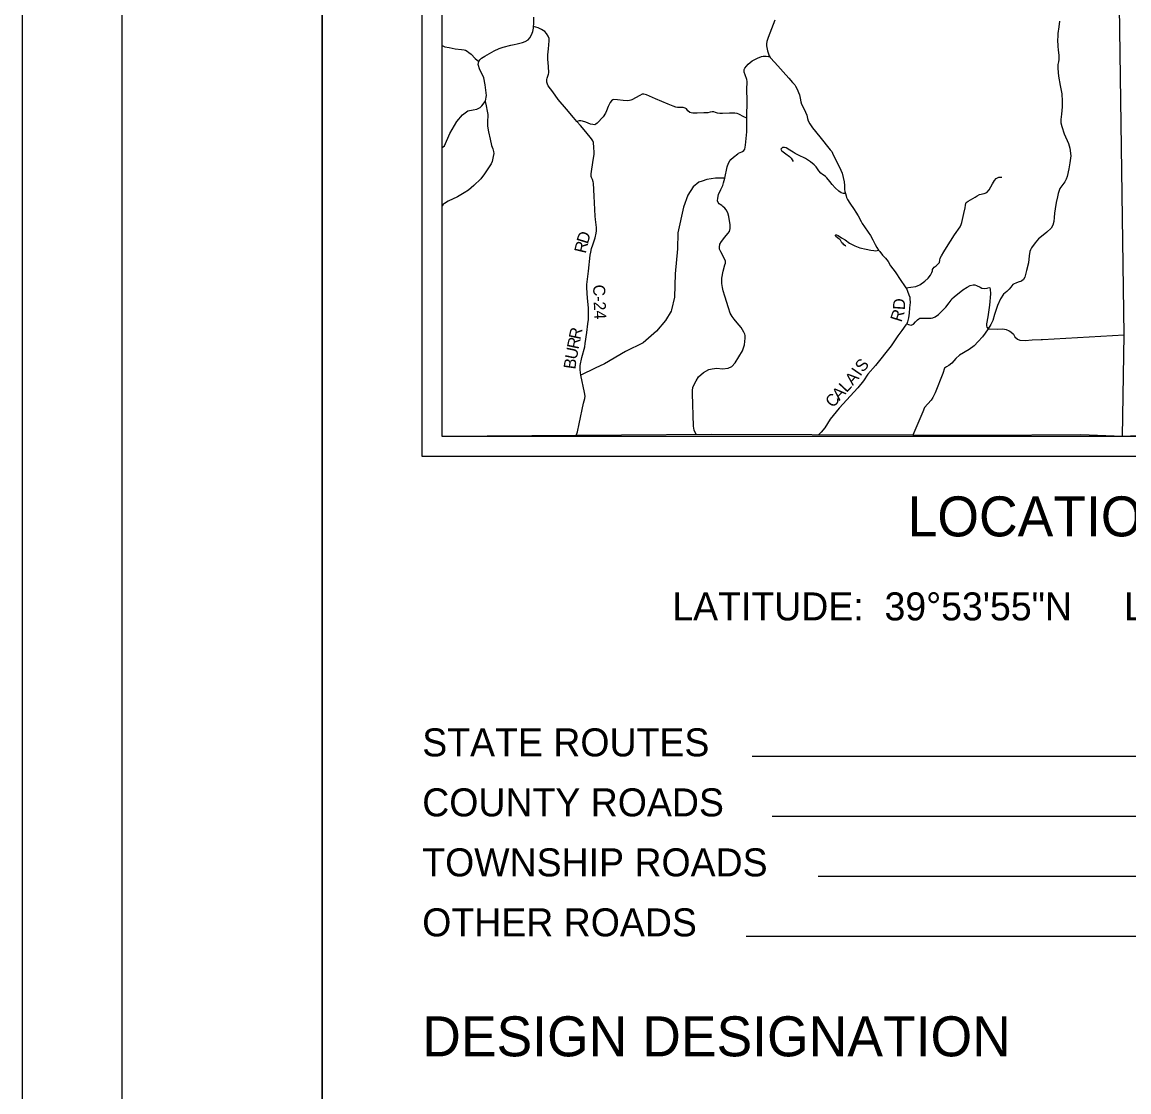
# Model space of a CAD drawing. Extents: x 0 to 2329303, y 0 to 694397.
# Drawn here: x 0 to 5.53, y 10.82 to 16.17 of the extents above; entities that cross this region are included whole.
import ezdxf

# ---------------------------------------------------------------- set-up
doc = ezdxf.new("R2010")
doc.units = 0
for name, color, linetype in [('GM_X_County_Road', 7, 'Continuous'), ('GM_X_County_Road_Text', 7, 'Continuous'), ('GM_X_State_Route', 7, 'Continuous'), ('GM_X_Township', 7, 'Continuous'), ('GM_X_Township_Road', 7, 'Continuous'), ('GM_X_Township_ROW', 7, 'Continuous'), ('SH_Border', 7, 'Continuous'), ('SH_Cut_Line', 7, 'Continuous'), ('SH_Data', 7, 'Continuous')]:
    doc.layers.add(name, color=color, linetype=linetype)

msp = doc.modelspace()

# ---------------------------------------------------------------- linework, layer by layer
at = {"layer": 'GM_X_County_Road'}
for points in [[(3.7623, 16.1817), (3.7466, 16.1383), (3.7289, 16.0945), (3.7227, 16.0744), (3.7203, 16.0635), (3.7204, 16.0523), (3.7266, 16.0275), (3.7315, 16.0135), (3.734, 16.0023)], [(2.77, 14.1049), (2.7767, 14.1234), (2.7842, 14.1622), (2.8067, 14.2655), (2.8125, 14.2901), (2.8138, 14.3009), (2.8114, 14.3189), (2.7927, 14.4063), (2.7892, 14.433), (2.7898, 14.4547), (2.7972, 14.495), (2.8123, 14.5475), (2.8145, 14.5652), (2.8233, 14.6198), (2.8286, 14.6635), (2.8312, 14.6844), (2.8319, 14.6992), (2.8318, 14.7124), (2.8304, 14.7429), (2.8265, 14.791), (2.8221, 14.8435), (2.8228, 14.8595), (2.8311, 14.9265), (2.8397, 15.0055), (2.8424, 15.0212), (2.8463, 15.04), (2.8534, 15.0585), (2.8651, 15.0931), (2.8702, 15.1164), (2.8717, 15.1288), (2.8716, 15.1453), (2.8665, 15.1845), (2.864, 15.2021), (2.8592, 15.3019), (2.8564, 15.3656), (2.8547, 15.3736), (2.8506, 15.3844), (2.8462, 15.394), (2.8445, 15.4004), (2.8448, 15.4128), (2.8551, 15.4811), (2.859, 15.5091), (2.8593, 15.522), (2.8579, 15.5444), (2.8561, 15.5693), (2.8537, 15.5781), (2.8468, 15.5888), (2.8177, 15.6227), (2.7918, 15.6542), (2.7733, 15.6749), (2.7563, 15.6944), (2.7216, 15.7366), (2.6796, 15.7844), (2.6525, 15.8223), (2.6298, 15.8538), (2.6266, 15.8614), (2.6237, 15.8706), (2.6232, 15.8846), (2.6248, 15.8914), (2.6279, 15.9015), (2.631, 15.9111), (2.6322, 15.9187), (2.6307, 15.9492), (2.6277, 15.9856), (2.6283, 16.0081), (2.6313, 16.0374), (2.6342, 16.0779), (2.6341, 16.0899), (2.6301, 16.1015), (2.6216, 16.1143), (2.6127, 16.1242), (2.5962, 16.1353), (2.5797, 16.1432), (2.5569, 16.1499)], [(3.734, 16.0023), (3.74, 15.9947), (3.7626, 15.9696), (3.8321, 15.8912), (3.8507, 15.8705), (3.8619, 15.8585), (3.8668, 15.8518), (3.8729, 15.8394), (3.8855, 15.8078), (3.8893, 15.7918), (3.8934, 15.773), (3.8967, 15.761), (3.904, 15.747), (3.9162, 15.7211), (3.9219, 15.7063), (3.926, 15.6899), (3.9293, 15.6779), (3.9378, 15.6627), (3.9516, 15.6435), (3.988, 15.5977), (4.0397, 15.5332), (4.0469, 15.524), (4.0514, 15.516), (4.064, 15.4877), (4.0867, 15.4457), (4.099, 15.4158), (4.1051, 15.3942), (4.1097, 15.3725), (4.111, 15.3553), (4.1111, 15.3429), (4.1116, 15.3341), (4.1128, 15.3253), (4.1153, 15.3149), (4.119, 15.3029), (4.1215, 15.2953), (4.1255, 15.2853), (4.1381, 15.2657), (4.1591, 15.2342), (4.1681, 15.2207), (4.179, 15.2027), (4.194, 15.1748), (4.1997, 15.1644), (4.211, 15.148), (4.2296, 15.1205), (4.241, 15.1042), (4.2523, 15.0822), (4.2649, 15.059), (4.2726, 15.0447), (4.2815, 15.0319), (4.2872, 15.0247), (4.3017, 15.0068), (4.3159, 14.9905), (4.3288, 14.9741), (4.341, 14.9522), (4.364, 14.9223), (4.3923, 14.8804), (4.4109, 14.8533), (4.4182, 14.8425), (4.4219, 14.8361), (4.4264, 14.8257), (4.4333, 14.8082), (4.437, 14.7958), (4.4382, 14.7882), (4.4388, 14.7697), (4.4366, 14.7428), (4.4335, 14.716), (4.4309, 14.6927), (4.4278, 14.6794), (4.4258, 14.6734), (4.4223, 14.6634), (4.418, 14.6572), (4.3973, 14.6295), (4.3783, 14.6033), (4.3439, 14.5522), (4.2651, 14.4544), (4.2277, 14.4117), (4.2057, 14.3783), (4.1778, 14.3431), (4.0851, 14.2412), (4.0388, 14.1855), (4.0119, 14.1435), (3.9936, 14.121), (3.9859, 14.1134), (3.9802, 14.1078)]]:
    msp.add_lwpolyline(points, dxfattribs=at)
at = {"layer": 'GM_X_State_Route'}
msp.add_lwpolyline([(2.1, 15.5452), (2.1109, 15.5534), (2.1388, 15.6142), (2.173, 15.6749), (2.2012, 15.7083), (2.2272, 15.7273), (2.2548, 15.7326), (2.2723, 15.7362), (2.2894, 15.7449), (2.298, 15.7535), (2.314, 15.7754), (2.3156, 15.7775), (2.3206, 15.8049), (2.314, 15.8574), (2.3073, 15.8928), (2.2947, 15.9215), (2.2873, 15.9337), (2.28, 15.9592), (2.2825, 15.9749), (2.2883, 15.983), (2.2966, 15.992), (2.3124, 16.0019), (2.3595, 16.0285), (2.3849, 16.0402), (2.4048, 16.0471), (2.4423, 16.0566), (2.4598, 16.0606), (2.4746, 16.0629), (2.5017, 16.069), (2.5148, 16.0741), (2.5294, 16.0836), (2.5385, 16.0938), (2.5462, 16.1076), (2.5527, 16.1249), (2.556, 16.141), (2.5569, 16.1499), (2.5583, 16.1639), (2.5581, 16.1964)], dxfattribs=at)
at = {"layer": 'GM_X_Township'}
for points in [[(5.8223, 14.1123), (5.5, 14.1), (5.5092, 14.6075), (5.4849, 16.2502), (5.4862, 16.3702), (5.4966, 17.3083), (5.484, 18.4012), (5.4927, 19.2711), (5.4941, 19.3381), (5.4896, 19.5547), (5.4893, 19.9096), (5.4898, 20.0261), (5.5032, 20.182), (5.5028, 20.3048), (5.5027, 20.3409), (5.5308, 20.3409), (5.6417, 20.3416)], [(5.5, 14.1), (5.293, 14.1081), (4.8004, 14.1048), (4.4533, 14.1061), (3.4443, 14.1098), (2.1, 14.1)]]:
    msp.add_lwpolyline(points, dxfattribs=at)
at = {"layer": 'GM_X_Township_Road'}
for points in [[(5.1861, 16.1763), (5.1826, 16.1481), (5.1781, 16.1144), (5.177, 16.1003), (5.1759, 16.083), (5.1766, 16.0518), (5.1788, 16.0315), (5.1829, 16.006), (5.1832, 15.996), (5.1828, 15.9844), (5.1803, 15.9731), (5.178, 15.9602), (5.1778, 15.9393), (5.1803, 15.901), (5.189, 15.854), (5.1976, 15.8134), (5.1979, 15.8034), (5.1993, 15.7859), (5.1993, 15.7474), (5.1961, 15.7109), (5.1918, 15.6855), (5.1923, 15.6687), (5.1974, 15.6496), (5.2086, 15.6124), (5.2313, 15.5643), (5.2381, 15.5409), (5.2422, 15.503), (5.2369, 15.4675), (5.2319, 15.4385), (5.2243, 15.4002), (5.2192, 15.3865), (5.2124, 15.3734), (5.2017, 15.3595), (5.1879, 15.339), (5.1783, 15.3146), (5.1749, 15.2985), (5.1698, 15.2699), (5.1645, 15.2385), (5.1612, 15.2164), (5.1595, 15.1943), (5.1574, 15.1742), (5.1524, 15.1556), (5.1433, 15.1409), (5.1231, 15.1218), (5.104, 15.1055), (5.0814, 15.0884), (5.0633, 15.0682), (5.0465, 15.0432), (5.0404, 15.0322), (5.0379, 15.0245), (5.0346, 15.0031), (5.0302, 14.9678), (5.0214, 14.9302), (5.0117, 14.8971), (5.0053, 14.8844), (4.996, 14.8761), (4.979, 14.8708), (4.9671, 14.8664), (4.9596, 14.8637), (4.9529, 14.8595), (4.9425, 14.8471), (4.9337, 14.836), (4.9217, 14.8244), (4.9061, 14.8115), (4.8905, 14.7886), (4.876, 14.7552), (4.8611, 14.7095), (4.8525, 14.6792), (4.8427, 14.6604), (4.8298, 14.638), (4.8141, 14.6166), (4.8, 14.5982), (4.7797, 14.5738), (4.7589, 14.5532), (4.7338, 14.5346), (4.686, 14.5061), (4.668, 14.4904), (4.6478, 14.4666), (4.6317, 14.4553), (4.6202, 14.4486), (4.6116, 14.4412), (4.6027, 14.4141), (4.5635, 14.3181), (4.5533, 14.2941), (4.544, 14.2811), (4.5109, 14.2441), (4.5018, 14.2234), (4.4724, 14.1533), (4.4533, 14.1061)], [(2.1, 16.0547), (2.1135, 16.0487), (2.1339, 16.0445), (2.1652, 16.0375), (2.196, 16.0349), (2.2101, 16.0334), (2.2165, 16.0311), (2.2249, 16.0271), (2.2334, 16.0204), (2.2443, 16.0116), (2.2652, 15.9905), (2.2825, 15.9749)], [(3.3698, 14.1093), (3.3601, 14.1313), (3.356, 14.1518), (3.3504, 14.3147), (3.3504, 14.3275), (3.3532, 14.346), (3.3688, 14.3777), (3.3811, 14.3977), (3.4062, 14.42), (3.433, 14.4343), (3.4502, 14.4379), (3.4729, 14.4405), (3.5019, 14.4377), (3.5286, 14.4407), (3.548, 14.4493), (3.5652, 14.4681), (3.6013, 14.5284), (3.6113, 14.5579), (3.6144, 14.5912), (3.6139, 14.604), (3.613, 14.612), (3.6085, 14.6216), (3.5943, 14.644), (3.5741, 14.6687), (3.5596, 14.6866), (3.5487, 14.6993), (3.5398, 14.7169), (3.5304, 14.7429), (3.5131, 14.8021), (3.5045, 14.8273), (3.5004, 14.8441), (3.4979, 14.8653), (3.4973, 14.8918), (3.5038, 14.9271), (3.5132, 14.9576), (3.5156, 14.9661), (3.5155, 14.9757), (3.5065, 14.9973), (3.4931, 15.0236), (3.4866, 15.0364), (3.4854, 15.0456), (3.4881, 15.0605), (3.4968, 15.075), (3.5134, 15.0963), (3.5285, 15.1153), (3.5356, 15.125), (3.5387, 15.139), (3.5386, 15.1574), (3.5327, 15.1991), (3.527, 15.2179), (3.5197, 15.2323), (3.5124, 15.2418), (3.5031, 15.2502), (3.4975, 15.2554), (3.489, 15.2593), (3.4838, 15.2637), (3.4789, 15.2696), (3.4761, 15.2772), (3.4776, 15.2921), (3.4819, 15.3098), (3.4933, 15.3351), (3.502, 15.3552), (3.5063, 15.3677), (3.5121, 15.3918), (3.5249, 15.4484), (3.5316, 15.4657), (3.5375, 15.4777), (3.5423, 15.4846), (3.5554, 15.4959), (3.5773, 15.5133), (3.5817, 15.5161), (3.5969, 15.5231), (3.6017, 15.5251), (3.608, 15.53), (3.6124, 15.5364), (3.6158, 15.5557), (3.6222, 15.6235), (3.6234, 15.6744), (3.6225, 15.6916), (3.6227, 15.7149), (3.6236, 15.759), (3.6241, 15.7946), (3.6224, 15.8195), (3.6226, 15.8407), (3.6252, 15.8668), (3.6252, 15.8748), (3.6227, 15.8848), (3.6137, 15.9076), (3.61, 15.9216), (3.6091, 15.9344), (3.6119, 15.9417), (3.629, 15.9614), (3.6489, 15.978), (3.6768, 15.991), (3.6964, 15.9992), (3.7036, 16.0009), (3.7112, 16.0017), (3.7192, 16.0006), (3.7292, 16.0003), (3.734, 16.0023)], [(2.314, 15.7754), (2.3198, 15.7524), (2.3244, 15.7272), (2.3273, 15.7092), (2.3278, 15.6976), (2.3267, 15.6811), (2.3256, 15.6663), (2.3257, 15.6515), (2.3311, 15.6238), (2.339, 15.5858), (2.3469, 15.5546), (2.3526, 15.5378), (2.3563, 15.525), (2.3576, 15.515), (2.3549, 15.4994), (2.3494, 15.4741), (2.3443, 15.4632), (2.3114, 15.4129), (2.2928, 15.3887), (2.2586, 15.3543), (2.2319, 15.3321), (2.2104, 15.3175), (2.1757, 15.298), (2.129, 15.276), (2.1107, 15.2654), (2.1043, 15.2606), (2.1, 15.2533)], [(3.6225, 15.6916), (3.608, 15.6979), (3.5835, 15.711), (3.5747, 15.7145), (3.5634, 15.7164), (3.5362, 15.7158), (3.5014, 15.7144), (3.4882, 15.7147), (3.4753, 15.7166), (3.4657, 15.7205), (3.4577, 15.7233), (3.4497, 15.7236), (3.4389, 15.7211), (3.4277, 15.7182), (3.4077, 15.7173), (3.3752, 15.7166), (3.352, 15.7164), (3.3444, 15.7176), (3.3376, 15.7204), (3.3279, 15.7287), (3.3206, 15.7375), (3.3142, 15.7418), (3.3038, 15.7446), (3.2869, 15.7452), (3.2765, 15.7452), (3.2685, 15.7463), (3.2549, 15.751), (3.2291, 15.762), (3.1669, 15.7888), (3.1215, 15.8077), (3.1139, 15.8105), (3.1079, 15.8116), (3.0995, 15.8108), (3.0871, 15.8051), (3.0484, 15.7839), (3.0428, 15.7815), (3.0364, 15.7798), (3.026, 15.7786), (3.004, 15.7804), (2.9755, 15.783), (2.9583, 15.7841), (2.9523, 15.7828), (2.9467, 15.7784), (2.9396, 15.7703), (2.9293, 15.7498), (2.9214, 15.7285), (2.9159, 15.7168), (2.9053, 15.6979), (2.8742, 15.6664), (2.8687, 15.6615), (2.8623, 15.6587), (2.8531, 15.659), (2.8414, 15.6617), (2.8177, 15.6716), (2.8005, 15.6767), (2.7925, 15.6782), (2.7853, 15.6782), (2.7733, 15.6749)], [(4.1153, 15.3149), (4.1053, 15.3148), (4.0949, 15.3179), (4.0832, 15.3271), (4.0647, 15.3434), (4.0497, 15.3593), (4.0368, 15.3748), (4.0223, 15.3923), (4.0162, 15.3991), (4.0094, 15.4055), (4.0009, 15.4102), (3.9933, 15.4158), (3.9832, 15.4277), (3.969, 15.4477), (3.9601, 15.4584), (3.9416, 15.4731), (3.9159, 15.489), (3.8817, 15.5067), (3.8648, 15.5146), (3.8548, 15.5206), (3.8379, 15.5321), (3.8194, 15.5424), (3.8113, 15.5451), (3.8065, 15.5455), (3.8013, 15.5442), (3.797, 15.541), (3.7934, 15.5357), (3.7954, 15.5289), (3.8043, 15.5238), (3.8184, 15.5127), (3.8361, 15.4996), (3.8442, 15.4908), (3.8547, 15.4753)], [(3.5121, 15.3918), (3.4655, 15.3921), (3.4226, 15.3847), (3.3998, 15.3767)], [(4.608, 15.0235), (4.621, 15.0441), (4.6614, 15.1077), (4.6887, 15.1488), (4.6939, 15.1592), (4.6982, 15.1701), (4.7083, 15.2147), (4.7137, 15.2424), (4.7152, 15.2568), (4.7167, 15.2644), (4.7191, 15.2701), (4.7299, 15.2766), (4.7522, 15.2891), (4.7634, 15.2966), (4.774, 15.3025), (4.7862, 15.3089), (4.8096, 15.3145), (4.8219, 15.3189), (4.8346, 15.3325), (4.8504, 15.3635), (4.8603, 15.3798), (4.8696, 15.3894), (4.8822, 15.3958), (4.8981, 15.3971)], [(4.1176, 15.0499), (4.1152, 15.0523), (4.1083, 15.0583), (4.1035, 15.0626), (4.0971, 15.0682), (4.0906, 15.0806), (4.0877, 15.0846), (4.0829, 15.0877), (4.0672, 15.0993), (4.0652, 15.1028), (4.0656, 15.1057), (4.0675, 15.1081), (4.0715, 15.1085), (4.0788, 15.105), (4.0965, 15.0931), (4.1142, 15.0824), (4.1359, 15.0669), (4.162, 15.0531), (4.1869, 15.0436), (4.2198, 15.0359), (4.2427, 15.0316), (4.2571, 15.0293), (4.2679, 15.0286), (4.2815, 15.0319)], [(4.4786, 14.8541), (4.4788, 14.8542), (4.4882, 14.8575), (4.5129, 14.8765), (4.5296, 14.8918), (4.5407, 14.9056), (4.5474, 14.9192), (4.5502, 14.9285), (4.5509, 14.9345), (4.5537, 14.9397), (4.5584, 14.9458), (4.5684, 14.9523), (4.5799, 14.9624), (4.5859, 14.97), (4.5882, 14.9821), (4.5897, 14.9917), (4.5953, 15.0034), (4.608, 15.0235)], [(4.4182, 14.8425), (4.443, 14.8467), (4.467, 14.8501), (4.4786, 14.8541)], [(4.4223, 14.6634), (4.4316, 14.659), (4.4448, 14.6571), (4.4564, 14.662), (4.4663, 14.6733), (4.4754, 14.6834), (4.4818, 14.6879), (4.4882, 14.6907), (4.5034, 14.6908), (4.5447, 14.6907), (4.5518, 14.6928), (4.565, 14.6977), (4.581, 14.7102), (4.6167, 14.7466), (4.6342, 14.7676), (4.6437, 14.7813), (4.6473, 14.7877), (4.6592, 14.7982), (4.7018, 14.833), (4.7237, 14.8464), (4.7393, 14.8541), (4.7541, 14.8578), (4.7625, 14.8579), (4.7701, 14.8548), (4.7894, 14.8457), (4.798, 14.8408), (4.8129, 14.8389), (4.8244, 14.8416), (4.8327, 14.8443), (4.8367, 14.8428), (4.8397, 14.8361), (4.8413, 14.8126), (4.8364, 14.7555), (4.8267, 14.6979), (4.8206, 14.6633), (4.8202, 14.6529), (4.8232, 14.6458), (4.8298, 14.638), (4.8735, 14.6366), (4.9023, 14.6372), (4.9195, 14.6345), (4.9337, 14.6286), (4.9423, 14.6237), (4.9551, 14.6109), (4.9627, 14.5976), (4.9755, 14.5856), (4.9873, 14.5815), (5.0134, 14.5799), (5.049, 14.5822), (5.0947, 14.5851), (5.1007, 14.5854)], [(3.2464, 14.7333), (3.2464, 14.7332), (3.2449, 14.7265), (3.2159, 14.6797), (3.1704, 14.6259), (3.1052, 14.5686), (3.0165, 14.5241), (2.9116, 14.4628), (2.8651, 14.4407), (2.865, 14.4406)], [(2.865, 14.4406), (2.7927, 14.4063)]]:
    msp.add_lwpolyline(points, dxfattribs=at)
at = {"layer": 'GM_X_Township_ROW'}
for points in [[(3.3998, 15.3767), (3.3996, 15.3766), (3.3831, 15.3709), (3.3537, 15.3472), (3.3279, 15.307), (3.3057, 15.2471), (3.2781, 15.1176), (3.2761, 15.0381), (3.265, 14.9122), (3.2603, 14.7962), (3.2464, 14.7333)], [(5.1007, 14.5854), (5.5092, 14.6075)]]:
    msp.add_lwpolyline(points, dxfattribs=at)
at = {"layer": 'SH_Border'}
for points in [[(0.5, 21.5), (1.5, 21.5), (1.5, 0.5), (0.5, 0.5)], [(1.5, 21.5), (33.5, 21.5), (33.5, 0.5), (1.5, 0.5)]]:
    msp.add_lwpolyline(points, close=True, dxfattribs=at)
at = {"layer": 'SH_Cut_Line'}
msp.add_lwpolyline([(0, 0), (34, 0), (34, 22), (0, 22)], close=True, dxfattribs=at)
at = {"layer": 'SH_Data'}
for p, q in [((7.68, 12.5), (3.65, 12.5)), ((7.68, 12.2), (3.75, 12.2)), ((7.68, 11.9), (3.98, 11.9)), ((7.68, 11.6), (3.62, 11.6))]:
    msp.add_line(p, q, dxfattribs=at)
for points in [[(2, 21), (9, 21), (9, 14), (2, 14)], [(2.1, 20.9), (8.9, 20.9), (8.9, 14.1), (2.1, 14.1)]]:
    msp.add_lwpolyline(points, close=True, dxfattribs=at)

# ---------------------------------------------------------------- texts
at = {"layer": 'GM_X_County_Road_Text'}
for s, rotation, p in [('D', 72.9222, (2.8274, 15.0591)), ('R', 76.6321, (2.8171, 15.012)), ('C-24', 272.3418, (2.8538, 14.8578)), ('D', 86.1508, (4.412, 14.7307)), ('R', 72.3871, (4.3953, 14.6683)), ('R', 78.2514, (2.7903, 14.5814)), ('R', 78.2522, (2.7811, 14.533)), ('U', 78.4064, (2.7714, 14.4811)), ('B', 81.6138, (2.7651, 14.4331)), ('I', 55.3692, (4.1903, 14.3976)), ('S', 49.8574, (4.2031, 14.4169)), ('A', 49.4204, (4.1526, 14.3515)), ('A', 46.8601, (4.0852, 14.2768)), ('L', 46.9747, (4.1207, 14.316)), ('C', 48.2611, (4.0533, 14.2398))]:
    msp.add_text(s, height=0.06, rotation=rotation, dxfattribs=at).set_placement(p)
at = {"layer": 'SH_Data'}
for s, height, p in [('LOCATION MAP', 0.2, (4.4265, 13.6)), ('LATITUDE:  39°53\'55"N     LONGITUDE:  81°13\'40"W', 0.14, (3.25, 13.18)), ('STATE ROUTES', 0.14, (2, 12.5)), ('COUNTY ROADS', 0.14, (2, 12.2)), ('TOWNSHIP ROADS', 0.14, (2, 11.9)), ('OTHER ROADS', 0.14, (2, 11.6)), ('DESIGN DESIGNATION', 0.2, (2, 11))]:
    msp.add_text(s, height=height, dxfattribs=at).set_placement(p)

doc.saveas('drawing.dxf')
